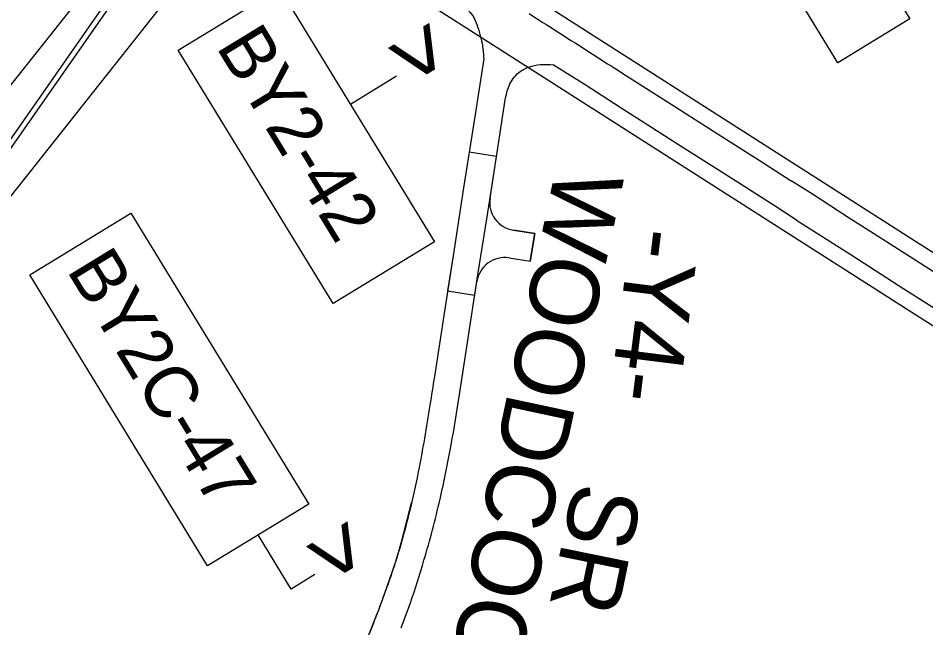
# Model space of a CAD drawing. Extents: x 1771071 to 1790027, y 804210 to 823391.
# Drawn here: x 1782402 to 1783049, y 813782 to 814217 of the extents above; entities that cross this region are included whole.
import ezdxf

# ---------------------------------------------------------------- set-up
doc = ezdxf.new("R2010")
doc.units = 0
for name, color, linetype in [('Default', 7, 'Continuous'), ('Exist Roads EOP', 7, 'Continuous'), ('Old_Level_57', 7, 'Continuous'), ('Prop Conc 5in Monolithic Surface Mount Island', 7, 'Continuous'), ('Prop Dimension Text', 7, 'Continuous'), ('Proposed Right of Way Monument PSD Text', 7, 'Continuous'), ('Scratch_Level_1', 7, 'Continuous'), ('Scratch_Level_7', 7, 'Continuous'), ('Scratch_Level_8', 7, 'Continuous')]:
    doc.layers.add(name, color=color, linetype=linetype)

msp = doc.modelspace()

# ---------------------------------------------------------------- linework, layer by layer
at = {"layer": 'Default'}
for points in [[(1782939.86, 814376.33), (1783037.78, 814216.07), (1782986.58, 814184.78), (1782888.66, 814345.05)], [(1782588.69, 814237.9), (1782699.11, 814057.19), (1782626.99, 814013.12), (1782516.58, 814193.83)], [(1782482.87, 814077.57), (1782609.56, 813870.23), (1782537.44, 813826.17), (1782410.75, 814033.51)]]:
    msp.add_lwpolyline(points, close=True, dxfattribs=at)
for points in [[(1782672.16, 814175.21), (1782639.28, 814155.11)], [(1782613.84, 813819.89), (1782596.91, 813809.6), (1782573.5, 813848.2)]]:
    msp.add_lwpolyline(points, dxfattribs=at)
at = {"layer": 'Exist Roads EOP'}
msp.add_line((1782675.37, 813782.04), (1782682.09, 813799.73), dxfattribs=at)
for points in [[(1782734.23, 814187.61), (1782728.02, 814148.04), (1782722.36, 814112.03), (1782719.85, 814095.74), (1782712.33, 814047.16), (1782706.26, 814007.67), (1782699.07, 813961.06)], [(1782716.95, 813948.36), (1782722.21, 813982.3), (1782730.09, 814033.69), (1782736.6, 814075.08), (1782743.83, 814120.73), (1782749.51, 814158.26)]]:
    msp.add_lwpolyline(points, dxfattribs=at)
for points in [[(1781123.7, 814794.56), (1781151.95, 814749.7), (1781175.35, 814711.94), (1781204.02, 814667.22), (1781230.05, 814626.42), (1781255.51, 814585.11), (1781282.93, 814541.39), (1781309.04, 814500.81), (1781338.07, 814453.82), (1781362.44, 814415.66), (1781389.1, 814373.22), (1781417.2, 814328.4), (1781443.82, 814286), (1781469.22, 814245.27), (1781496.33, 814201.88), (1781523.28, 814159.28), (1781551.49, 814114.9), (1781575, 814076.8), (1781602.27, 814034.47), (1781628.68, 813992.42), (1781657.71, 813946.44), (1781682.97, 813906.24), (1781710.54, 813862.11), (1781734.73, 813823.58), (1781763.09, 813779.24), (1781788.41, 813738.38), (1781814.81, 813696.35), (1781842.37, 813653.36), (1781868.91, 813610.68), (1781895.83, 813568.71), (1781924.39, 813523.58), (1781950.61, 813481.8), (1781976.68, 813442.67), (1782004.37, 813401.37), (1782031.99, 813360.12), (1782060.77, 813317.53), (1782089.19, 813276.64), (1782119.2, 813233.31), (1782146.2, 813195.67), (1782175.13, 813155.14), (1782204.07, 813115.4), (1782233.24, 813075.72), (1782263.79, 813034.43), (1782294.03, 812994.29), (1782325.04, 812953.86), (1782354.41, 812916.21), (1782385, 812877.38), (1782417.21, 812837.26), (1782449.43, 812797.65), (1782479.54, 812761.76), (1782513.17, 812720.66), (1782543.05, 812684.98), (1782576.35, 812645.89), (1782608.48, 812608.74), (1782640.69, 812571.37), (1782677.39, 812530.96), (1782710.34, 812494.65), (1782741.2, 812460.83), (1782775.54, 812424.09), (1782810.15, 812387.02), (1782844.36, 812350.73), (1782880.69, 812313.19), (1782914.85, 812277.64), (1782949.87, 812242.16), (1782985.13, 812206.92), (1783022.44, 812170.42), (1783054.86, 812138.57), (1783094.75, 812100.54), (1783130.02, 812066.91), (1783162.74, 812036.24), (1783200.85, 812001.49), (1783239.6, 811965.96), (1783275.52, 811933.35), (1783312.46, 811900.79)], [(1782723.67, 814221.68), (1782727.13, 814216.98), (1782729.81, 814210.47), (1782732.01, 814203.23), (1782733.27, 814197.25), (1782734.23, 814187.61)], [(1782749.51, 814158.26), (1782752.31, 814168.4), (1782759.25, 814177.84), (1782766.38, 814181.76), (1782774.72, 814183.5), (1782783.77, 814183.36)], [(1782699.07, 813961.06), (1782695.87, 813940.8), (1782687.6, 813893.23), (1782679.87, 813859.05), (1782675.04, 813841.16), (1782666.84, 813815.75), (1782652.92, 813778.24)], [(1782682.09, 813799.73), (1782691.65, 813830.13), (1782703.07, 813873.65), (1782710.99, 813912.33), (1782716.95, 813948.36)]]:
    msp.add_spline(points, degree=3, dxfattribs=at)
at = {"layer": 'Prop Conc 5in Monolithic Surface Mount Island'}
for p, q in [((1782723.75, 814121.03), (1782719.85, 814095.74)), ((1782743.39, 814117.93), (1782723.75, 814121.03)), ((1782738.7, 814088.31), (1782743.39, 814117.93)), ((1782719.85, 814095.74), (1782712.33, 814047.16)), ((1782755.33, 814065.43), (1782770.52, 814063.03)), ((1782770.52, 814063.03), (1782767.41, 814043.28)), ((1782712.33, 814047.16), (1782708.5, 814022.2)), ((1782752.25, 814045.67), (1782767.41, 814043.28)), ((1782727.86, 814019.14), (1782729.36, 814028.94)), ((1782708.5, 814022.2), (1782727.86, 814019.14))]:
    msp.add_line(p, q, dxfattribs=at)
for centre, start, end in [((1782758.45, 814085.18), 171.00203, 261.03336), ((1782749.13, 814025.91), 81.03336, 171.28117)]:
    msp.add_arc(centre, 20, start, end, dxfattribs=at)
at = {"layer": 'Prop Dimension Text'}
for p, q in [((1782465.41, 814228.41), (1782350.67, 814064.15)), ((1782353.82, 814061.69), (1782468.56, 814225.95))]:
    msp.add_line(p, q, dxfattribs=at)
at = {"layer": 'Scratch_Level_1'}
msp.add_line((1782784.48, 814182.91), (1782783.77, 814183.36), dxfattribs=at)
for points in [[(1782957.05, 814072.69), (1782941.75, 814082.49), (1782904.59, 814106.27), (1782872.37, 814126.89), (1782853.79, 814138.65), (1782835.42, 814150.23), (1782806.48, 814168.98), (1782784.48, 814182.91)], [(1782832.73, 814177.58), (1782865.06, 814156.93), (1782903.76, 814132.24), (1782930.45, 814115.26), (1782953.36, 814100.59)], [(1782832.14, 814152.35), (1782831.59, 814152.71)], [(1782856.81, 814136.57), (1782856.34, 814136.87)], [(1783312.22, 813870.98), (1783270.66, 813897.48), (1783229.11, 813924.07), (1783187.82, 813950.57), (1783145.4, 813977.8), (1783102.46, 814005.18), (1783062.43, 814030.76), (1783037.57, 814046.7), (1783010.11, 814064.34), (1782994.61, 814073.9), (1782968.36, 814091.08), (1782953.36, 814100.59)], [(1782957.05, 814072.69), (1782997.32, 814047.07), (1783033.64, 814023.73), (1783053.56, 814011.03), (1783077.16, 813995.81), (1783116.5, 813970.95), (1783156.27, 813945.27), (1783197.33, 813919.23), (1783238.94, 813892.35), (1783280.65, 813865.79), (1783320.67, 813840.18), (1783362.13, 813813.73), (1783381.93, 813800.87)], [(1782682.52, 813871.32), (1782679.39, 813859), (1782675.06, 813842.21), (1782672.19, 813831.96), (1782668.92, 813822.02), (1782663.28, 813805.79), (1782658.53, 813792.76)], [(1782623.35, 813704.26), (1782623.39, 813704.36), (1782626.9, 813713.77), (1782632.27, 813727.44), (1782636.31, 813737.6), (1782641.85, 813750.8), (1782647.94, 813765.44), (1782653.31, 813779.27), (1782658.53, 813792.76)]]:
    msp.add_lwpolyline(points, dxfattribs=at)
msp.add_spline([(1782766.5, 814219.88), (1782791.69, 814203.81), (1782832.73, 814177.58)], degree=3, dxfattribs=at)
at = {"layer": 'Scratch_Level_8'}
for p, q in [((1783161.34, 813981.02), (1782664.74, 814298.57)), ((1782641.03, 814261.5), (1783137.64, 813943.95)), ((1782464.72, 814254.56), (1781921.58, 813568.53)), ((1782274, 813933.92), (1782503.53, 814223.83)), ((1782723.75, 814121.03), (1782719.85, 814095.74)), ((1782743.39, 814117.93), (1782723.75, 814121.03)), ((1782738.7, 814088.31), (1782743.39, 814117.93)), ((1782719.85, 814095.74), (1782712.33, 814047.16)), ((1782770.52, 814063.03), (1782755.33, 814065.43)), ((1782767.41, 814043.28), (1782770.52, 814063.03)), ((1782712.33, 814047.16), (1782708.5, 814022.2)), ((1782752.25, 814045.67), (1782767.41, 814043.28)), ((1782727.86, 814019.14), (1782729.36, 814028.94)), ((1782708.5, 814022.2), (1782727.86, 814019.14))]:
    msp.add_line(p, q, dxfattribs=at)
for centre, start, end in [((1782758.45, 814085.18), 171.00203, 261.03336), ((1782749.13, 814025.91), 81.03336, 171.28117)]:
    msp.add_arc(centre, 20, start, end, dxfattribs=at)

# ---------------------------------------------------------------- texts
at = {"layer": 'Old_Level_57'}
for p in [(1782659.92, 814195.24), (1782601.62, 813839.88)]:
    msp.add_text('>', height=46.95, rotation=301.43915, dxfattribs=at).set_placement(p)
at = {"layer": 'Proposed Right of Way Monument PSD Text'}
for s, p in [('BY2-42', (1782543.04, 814196.28)), ('BY2C-47', (1782436.55, 814037.06))]:
    msp.add_text(s, height=37.325, rotation=301.42495, dxfattribs=at).set_placement(p)
at = {"layer": 'Scratch_Level_7'}
for s, height, rotation, p in [('WOODCOCK DR.', 49.2075, 257.92802, (1782786.04, 814112.16)), ('-Y4-', 49.208, 262.85009, (1782839.33, 814068.84)), ('SR 3592', 49.208, 258.49109, (1782799.05, 813887.33))]:
    msp.add_text(s, height=height, rotation=rotation, dxfattribs=at).set_placement(p)

doc.saveas('drawing.dxf')
